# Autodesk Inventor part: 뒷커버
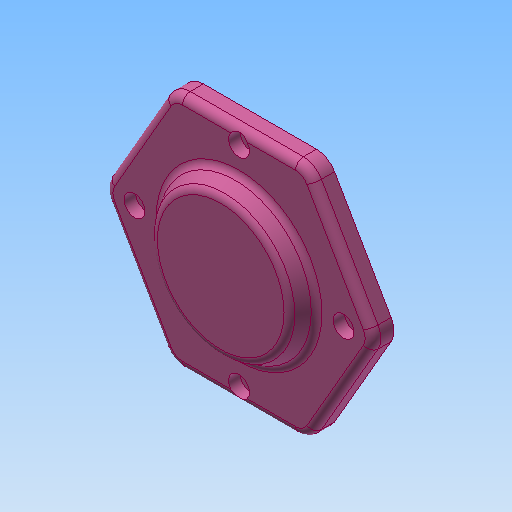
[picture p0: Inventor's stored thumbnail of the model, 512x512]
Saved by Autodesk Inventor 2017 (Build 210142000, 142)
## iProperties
Created: 2013-02
Part Number: 뒷커버
Document SubType Name: Modeling
Density: 1 g/cm^3
Material: 일반
Appearance: 분홍색
Author: 한국산업디자인학원[gmhk.co.kr]
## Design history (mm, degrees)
sketch "스케치1" dims "d37" = 105
  geometry: L1 (50.191, -4)-(28.559, -41.466); L2 (21.631, -45.466)-(-21.631, -45.466); L3 (-28.559, -41.466)-(-50.191, -4); L4 (-50.191, 4)-(-28.559, 41.466); L5 (-21.631, 45.466)-(21.631, 45.466); L6 (28.559, 41.466)-(50.191, 4); C1 r 30 at (0, 0); A1 r 8 centre (-21.631, 37.466) between (-21.631, 45.466) and (-28.559, 41.466); A2 r 8 centre (21.631, 37.466) between (28.559, 41.466) and (21.631, 45.466); A3 r 8 centre (43.262, 0) between (50.191, -4) and (50.191, 4); A4 r 8 centre (21.631, -37.466) between (21.631, -45.466) and (28.559, -41.466); A5 r 8 centre (-21.631, -37.466) between (-28.559, -41.466) and (-21.631, -45.466); A6 r 8 centre (-43.262, 0) between (-50.191, 4) and (-50.191, -4); 9 further points
  constraints: 12 end point, 12 point on circle, 12 point on line, 12 tangent, 7 centre point, 5 equal radius, 3 coincident, 1 horizontal, 1 horizontal alignment, 15 other
  dimensions: "d39" = 60 diameter of C1; "d40" = 8 radius of A1
extrude "돌출1" new body sketch "스케치1" distance "d0" = 8; taper "d1" = 0 deg
sketch "스케치2"
  geometry: C1 r 30 at (0, 0); 1 further point
  constraints: 1 centre point, 1 coincident
  dimensions: "d2" = 60 diameter of C1
extrude "돌출2" join sketch "스케치2" distance "d3" = 7; taper "d4" = -30 deg
sketch "스케치3"
  geometry: C1 r 30 at (0, 0) reference; A1 r 40 centre (0, 0) between (0, 40) and (-40, 0); 2 further points
  constraints: 4 point on circle, 2 horizontal alignment, 2 vertical alignment, 1 centre point, 1 coincident
  dimensions: "d47" = 80 diameter of A1
hole "구멍2" sketch "스케치3" at (0, 40), (-40, 0), (0, -40), (40, 0) diameter "d14" = 4.5; stored, may be unused: countersink angle "d18" = 90 deg, drill point angle "d20" = 118 deg; dims "d15" = 6, "d16" = 8, "d17" = 4.4, "d19" = 20
extrude "돌출3" join sketch "스케치1" distance "d21" = 12; taper "d22" = 0 deg
hole "구멍3" diameter "d25" = 30; stored, may be unused: countersink angle "d29" = 90 deg, drill point angle "d31" = 0 deg; dims "d26" = 6, "d27" = 42, "d28" = 13, "d30" = 16, "d50" = 10, "d51" = 10
fillet "모깎기1" dims "d32" = 3, "d33" = 1
chamfer "모따기1" distance "d34" = 1; stored, may be unused: second distance "d35" = 2, angle "d36" = 45 deg
chamfer "모따기2" distance "d43" = 1; stored, may be unused: second distance "d44" = 2, angle "d45" = 45 deg
fillet "모깎기2" dims "d46" = 3
node "솔리드1"
